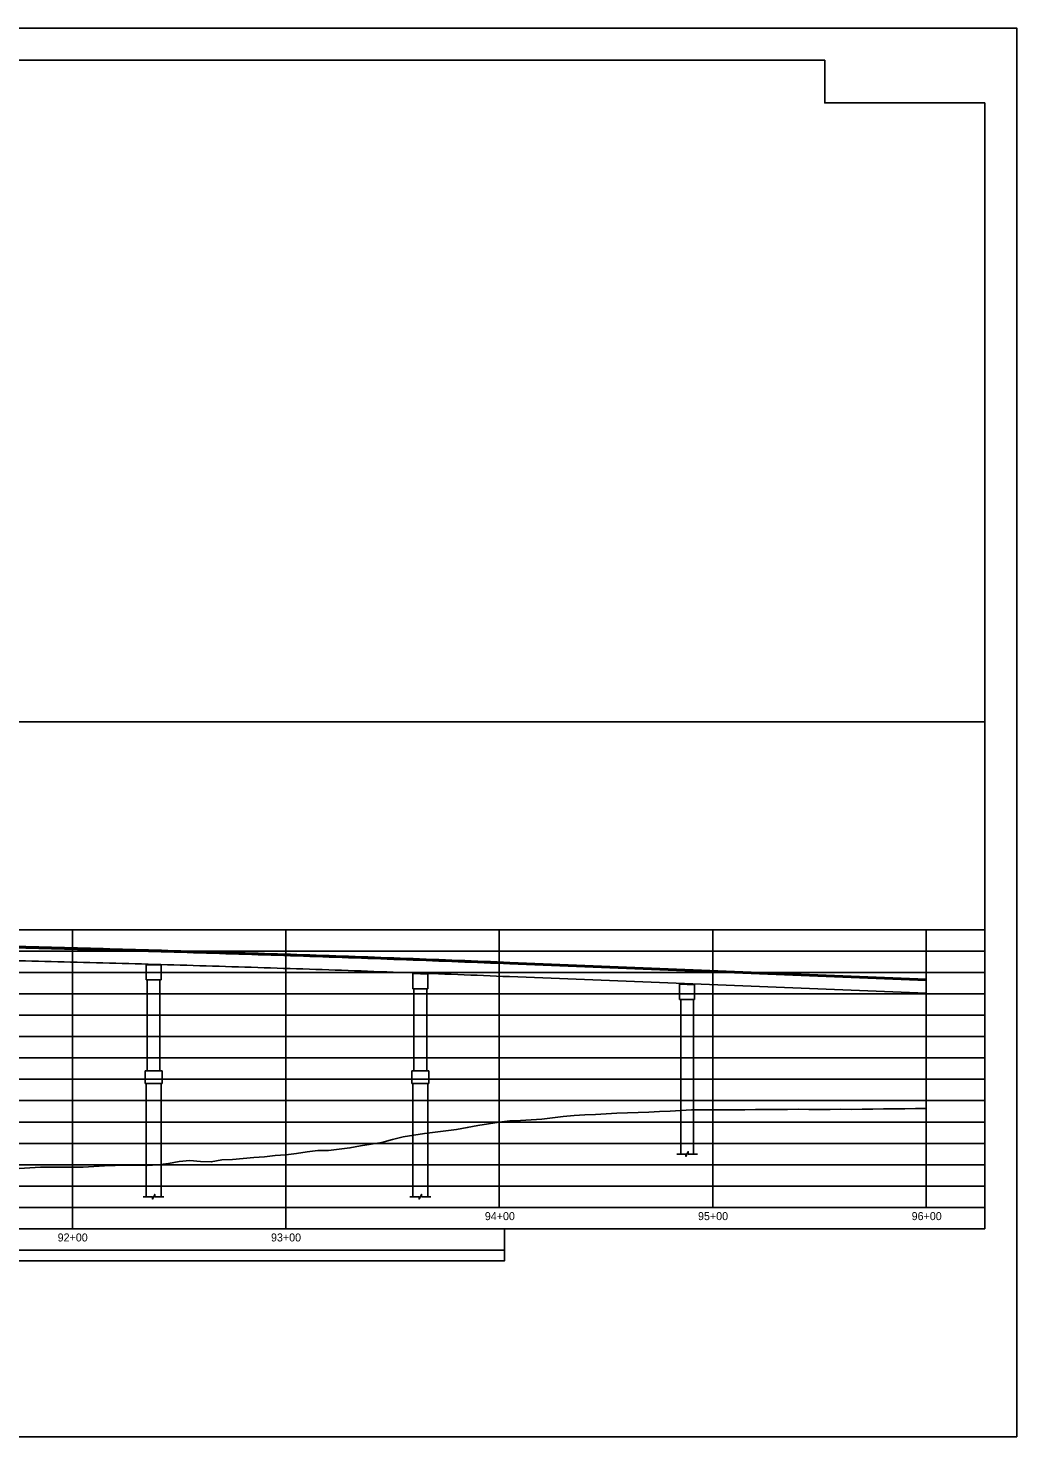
# Model space of a CAD drawing. Extents: x -464 to 4306, y -1372 to 300.
# Drawn here: x 2613 to 3076, y -1372 to -712 of the extents above; entities that cross this region are included whole.
import ezdxf

# ---------------------------------------------------------------- set-up
doc = ezdxf.new("R2010")
doc.units = 0
for name, color, linetype in [('BR_AUTO DIMENSION', 7, 'Continuous'), ('BR_BORDER LINES', 7, 'Continuous'), ('BR_GRID LINES', 7, 'Continuous'), ('BR_TEXT', 7, 'Continuous'), ('Mis Ground Lines', 7, 'Continuous'), ('NOPLOT', 7, 'Continuous'), ('Sheet Plot Border Outside CELL', 7, 'Continuous'), ('sub interior bent cap lines', 7, 'Continuous'), ('Sup Concrete Girder Lines', 7, 'Continuous'), ('Sup Concrete Slab Lines', 7, 'Continuous')]:
    doc.layers.add(name, color=color, linetype=linetype)

msp = doc.modelspace()

# ---------------------------------------------------------------- linework, layer by layer
at = {"layer": 'BR_AUTO DIMENSION'}
msp.add_line((3033.5, -1224.94), (3033.5, -1154.94), dxfattribs=at)
for points in [[(2916.62, -1239.94), (2920.94, -1239.94), (2920.94, -1241.06), (2922.06, -1238.83), (2922.06, -1239.94), (2926.37, -1239.94)], [(2666.62, -1259.94), (2670.94, -1259.94), (2670.94, -1261.06), (2672.06, -1258.83), (2672.06, -1259.94), (2676.37, -1259.94)], [(2791.62, -1259.94), (2795.94, -1259.94), (2795.94, -1261.06), (2797.06, -1258.83), (2797.06, -1259.94), (2801.37, -1259.94)]]:
    msp.add_lwpolyline(points, dxfattribs=at)
at = {"layer": 'BR_BORDER LINES'}
msp.add_line((2056, -1037.44), (3061, -1037.44), dxfattribs=at)
at = {"layer": 'BR_GRID LINES'}
for p, q in [((2056, -1134.94), (3061, -1134.94)), ((2633.5, -1274.94), (2633.5, -1134.94)), ((2733.5, -1274.94), (2733.5, -1134.94)), ((2833.5, -1264.94), (2833.5, -1134.94)), ((2933.5, -1264.94), (2933.5, -1134.94)), ((3033.5, -1264.94), (3033.5, -1134.94)), ((2056, -1144.94), (3061, -1144.94)), ((2056, -1154.94), (3061, -1154.94)), ((2056, -1164.94), (3061, -1164.94)), ((2056, -1174.94), (3061, -1174.94)), ((2056, -1184.94), (3061, -1184.94)), ((2056, -1194.94), (3061, -1194.94)), ((2056, -1204.94), (3061, -1204.94)), ((2056, -1214.94), (3061, -1214.94)), ((2056, -1224.94), (3061, -1224.94)), ((2056, -1234.94), (3061, -1234.94)), ((2056, -1244.94), (3061, -1244.94)), ((2056, -1254.94), (3061, -1254.94)), ((2056, -1264.94), (3061, -1264.94)), ((2056, -1274.94), (2836, -1274.94)), ((2056, -1284.94), (2836, -1284.94))]:
    msp.add_line(p, q, dxfattribs=at)
at = {"layer": 'Mis Ground Lines'}
for points in [[(2608.5, -1246.72), (2613.5, -1246.4), (2618.5, -1246.15), (2623.5, -1246.06), (2628.5, -1246.14), (2633.5, -1246.17), (2638.5, -1246.07), (2643.5, -1245.77), (2648.5, -1245.52), (2653.5, -1245.27), (2658.5, -1245.2), (2663.5, -1245.2), (2668.5, -1245.3), (2673.5, -1245.01), (2678.5, -1244.44), (2683.5, -1243.41), (2688.5, -1243.05), (2693.5, -1243.44), (2698.5, -1243.62), (2703.5, -1242.7), (2708.5, -1242.52), (2713.5, -1242.07), (2718.5, -1241.57), (2723.5, -1241.22), (2728.5, -1240.67), (2733.5, -1240.39), (2738.5, -1239.64), (2743.5, -1238.9), (2748.5, -1238.32), (2753.5, -1238.22), (2758.5, -1237.72), (2763.5, -1237.1), (2768.5, -1236.13), (2773.5, -1235.28), (2778.5, -1234.56), (2783.5, -1233.12), (2788.5, -1231.92), (2793.5, -1231.1), (2798.5, -1230.39), (2803.5, -1229.63), (2808.5, -1229.1), (2813.5, -1228.42), (2818.5, -1227.58), (2823.5, -1226.64), (2828.5, -1225.77), (2833.5, -1225.03), (2838.5, -1224.45), (2843.5, -1224.17), (2848.5, -1223.85), (2853.5, -1223.58), (2858.5, -1223.06), (2863.5, -1222.4), (2868.5, -1221.92), (2873.5, -1221.65), (2878.5, -1221.36), (2883.5, -1221.06), (2888.5, -1220.73), (2893.5, -1220.66), (2898.5, -1220.51), (2903.5, -1220.3), (2908.5, -1220.04), (2913.5, -1219.8), (2918.5, -1219.61), (2923.5, -1219.29), (2928.5, -1219.2), (2933.5, -1219.2)], [(2933.5, -1219.2), (2938.5, -1219.17), (2943.5, -1219.2), (2948.5, -1219.19), (2953.5, -1219.1), (2958.5, -1219.13), (2963.5, -1219.02), (2968.5, -1219.05), (2973.5, -1218.96), (2978.5, -1219.06), (2983.5, -1219.03), (2988.5, -1219.01), (2993.5, -1218.89), (2998.5, -1219.01), (3003.5, -1218.88), (3008.5, -1218.87), (3013.5, -1218.78), (3018.5, -1218.77), (3023.5, -1218.73), (3028.5, -1218.63), (3033.5, -1218.57)]]:
    msp.add_lwpolyline(points, dxfattribs=at)
at = {"layer": 'NOPLOT'}
msp.add_lwpolyline([(2101, -727.45), (2101, -734.19), (2056, -734.19), (2056, -1357.44), (2601.93, -1357.44), (2601.93, -1289.94), (2836, -1289.94), (2836, -1274.94), (3061, -1274.94), (3061, -747.45), (2986, -747.45), (2986, -727.45)], close=True, dxfattribs=at)
at = {"layer": 'Sheet Plot Border Outside CELL'}
msp.add_lwpolyline([(1996, -712.44), (3076, -712.44), (3076, -1372.44), (1996, -1372.44)], close=True, dxfattribs=at)
at = {"layer": 'sub interior bent cap lines'}
for p, q in [((2668, -1151.29), (2668, -1158.39)), ((2675, -1151.49), (2668, -1151.29)), ((2675, -1151.49), (2675, -1158.39)), ((2668, -1158.39), (2675, -1158.39)), ((2668.5, -1158.39), (2668.5, -1200.94)), ((2674.5, -1158.39), (2674.5, -1200.94)), ((2793, -1155.4), (2793, -1162.53)), ((2793, -1155.4), (2800, -1155.66)), ((2800, -1155.66), (2800, -1162.53)), ((2918, -1160.33), (2918, -1167.47)), ((2925, -1160.61), (2918, -1160.33)), ((2925, -1160.61), (2925, -1167.47)), ((2793, -1162.53), (2800, -1162.53)), ((2793.5, -1162.53), (2793.5, -1200.94)), ((2799.5, -1162.53), (2799.5, -1200.94)), ((2918, -1167.47), (2925, -1167.47)), ((2918.5, -1167.47), (2918.5, -1239.94)), ((2924.5, -1167.47), (2924.5, -1239.94)), ((2667.5, -1200.94), (2675.5, -1200.94)), ((2667.5, -1200.94), (2667.5, -1206.94)), ((2675.5, -1200.94), (2675.5, -1206.94)), ((2792.5, -1200.94), (2800.5, -1200.94)), ((2792.5, -1200.94), (2792.5, -1206.94)), ((2800.5, -1200.94), (2800.5, -1206.94)), ((2667.5, -1206.94), (2675.5, -1206.94)), ((2668, -1206.94), (2668, -1259.94)), ((2675, -1206.94), (2675, -1259.94)), ((2792.5, -1206.94), (2800.5, -1206.94)), ((2793, -1206.94), (2793, -1259.94)), ((2800, -1206.94), (2800, -1259.94))]:
    msp.add_line(p, q, dxfattribs=at)
at = {"layer": 'Sup Concrete Girder Lines'}
for p, q in [((2838.47, -1150.81), (3033.5, -1158.61)), ((2838.23, -1156.81), (3033.5, -1164.62))]:
    msp.add_line(p, q, dxfattribs=at)
for points in [[(2083.5, -1139.45), (2088.31, -1139.41), (2112.51, -1139.2), (2136.7, -1139.02), (2160.9, -1138.89), (2185.1, -1138.79), (2209.3, -1138.73), (2233.5, -1138.71), (2257.7, -1138.73), (2281.9, -1138.79), (2306.1, -1138.89), (2330.3, -1139.02), (2354.49, -1139.2), (2378.69, -1139.41), (2402.89, -1139.66), (2427.09, -1139.95), (2451.29, -1140.28), (2475.49, -1140.65), (2499.69, -1141.05), (2523.89, -1141.5), (2548.09, -1141.98), (2572.29, -1142.51), (2596.48, -1143.07), (2620.68, -1143.67), (2644.88, -1144.31), (2669.08, -1144.98), (2693.28, -1145.7), (2717.48, -1146.45), (2741.68, -1147.25), (2765.88, -1148.08), (2790.08, -1148.95), (2814.27, -1149.86), (2838.47, -1150.81)], [(2083.5, -1145.46), (2088.36, -1145.41), (2112.55, -1145.19), (2136.74, -1145.02), (2160.93, -1144.89), (2185.12, -1144.79), (2209.31, -1144.73), (2233.5, -1144.71), (2257.69, -1144.73), (2281.88, -1144.79), (2306.07, -1144.89), (2330.26, -1145.02), (2354.45, -1145.19), (2378.64, -1145.41), (2402.83, -1145.66), (2427.01, -1145.95), (2451.2, -1146.28), (2475.39, -1146.65), (2499.58, -1147.05), (2523.77, -1147.5), (2547.96, -1147.98), (2572.15, -1148.5), (2596.34, -1149.07), (2620.53, -1149.67), (2644.72, -1150.3), (2668.91, -1150.98), (2693.1, -1151.7), (2717.29, -1152.45), (2741.48, -1153.25), (2765.67, -1154.08), (2789.85, -1154.95), (2814.04, -1155.86), (2838.23, -1156.81)]]:
    msp.add_spline(points, degree=3, dxfattribs=at)
at = {"layer": 'Sup Concrete Slab Lines'}
msp.add_line((2838.5, -1150.14), (3033.5, -1157.94), dxfattribs=at)
msp.add_spline([(2083.5, -1138.79), (2088.3, -1138.74), (2112.5, -1138.53), (2136.7, -1138.35), (2160.9, -1138.22), (2185.1, -1138.12), (2209.3, -1138.06), (2233.5, -1138.04), (2257.7, -1138.06), (2281.9, -1138.12), (2306.1, -1138.22), (2330.3, -1138.35), (2354.5, -1138.53), (2378.7, -1138.74), (2402.9, -1138.99), (2427.1, -1139.28), (2451.3, -1139.61), (2475.5, -1139.98), (2499.7, -1140.39), (2523.9, -1140.83), (2548.1, -1141.32), (2572.3, -1141.84), (2596.5, -1142.4), (2620.7, -1143), (2644.9, -1143.64), (2669.1, -1144.32), (2693.3, -1145.03), (2717.5, -1145.79), (2741.7, -1146.58), (2765.9, -1147.41), (2790.1, -1148.29), (2814.3, -1149.2), (2838.5, -1150.14)], degree=3, dxfattribs=at)

# ---------------------------------------------------------------- texts
at = {"layer": 'BR_TEXT'}
for s, p in [('94+00', (2826.72, -1270.91)), ('95+00', (2926.61, -1270.91)), ('96+00', (3026.72, -1270.91)), ('92+00', (2626.55, -1280.91)), ('93+00', (2726.52, -1280.91))]:
    msp.add_text(s, height=3.75, rotation=360, dxfattribs=at).set_placement(p)

doc.saveas('drawing.dxf')
